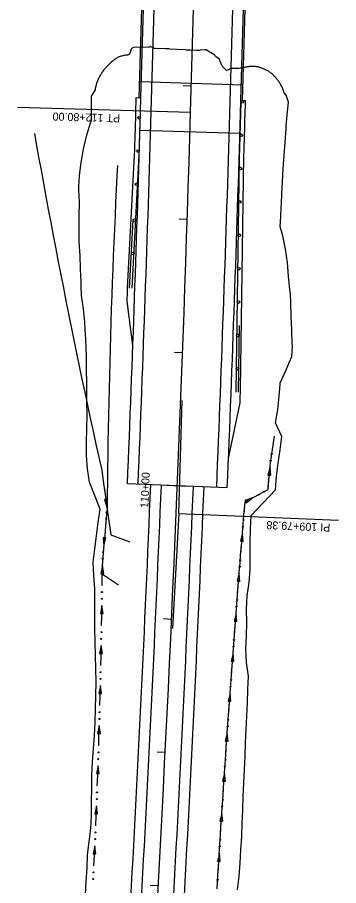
# Model space of a CAD drawing. Extents: x 1441466 to 1476381, y 2042742 to 2057194.
# Drawn here: x 1445977 to 1446218, y 2043457 to 2044108 of the extents above; entities that cross this region are included whole.
import ezdxf

# ---------------------------------------------------------------- set-up
doc = ezdxf.new("R2010")
doc.units = 0
for name, color, linetype in [('Default', 7, 'Continuous'), ('R_Bridge', 7, 'Continuous'), ('R_Guardrail', 7, 'Continuous'), ('R_Horz Alg', 7, 'Continuous'), ('R_Horz Alg Annot', 7, 'Continuous'), ('R_Horz Alg Stationing', 7, 'Continuous'), ('R_Proposed Const Limits', 7, 'Continuous'), ('R_Proposed Road', 7, 'Continuous'), ('R_Shld', 7, 'Continuous'), ('R_Special Ditch', 7, 'Continuous')]:
    doc.layers.add(name, color=color, linetype=linetype)

msp = doc.modelspace()

# ---------------------------------------------------------------- linework, layer by layer
at = {"layer": 'Default'}
for p, q in [((1446043.94, 2043747.07), (1446041.85, 2043746.77)), ((1446041.85, 2043746.77), (1446043.75, 2043740.98)), ((1446043.75, 2043740.98), (1446043.94, 2043747.07)), ((1446043.02, 2043717.95), (1446040.91, 2043718.13)), ((1446040.91, 2043718.13), (1446041.45, 2043712.06)), ((1446041.45, 2043712.06), (1446043.02, 2043717.95)), ((1446040.33, 2043697.27), (1446039.22, 2043691.28)), ((1446041.34, 2043691.26), (1446040.33, 2043697.27)), ((1446039.22, 2043691.28), (1446041.34, 2043691.26)), ((1446039.99, 2043667.23), (1446038.85, 2043661.25)), ((1446040.96, 2043661.22), (1446039.99, 2043667.23)), ((1446038.85, 2043661.25), (1446040.96, 2043661.22)), ((1446039.5, 2043637.2), (1446038.32, 2043631.22)), ((1446040.44, 2043631.18), (1446039.5, 2043637.2)), ((1446038.32, 2043631.22), (1446040.44, 2043631.18)), ((1446038.84, 2043607.18), (1446037.63, 2043601.21)), ((1446039.74, 2043601.15), (1446038.84, 2043607.18)), ((1446037.63, 2043601.21), (1446039.74, 2043601.15)), ((1446038.05, 2043577.15), (1446036.81, 2043571.19)), ((1446038.93, 2043571.12), (1446038.05, 2043577.15)), ((1446036.81, 2043571.19), (1446038.93, 2043571.12)), ((1446037.09, 2043547.13), (1446035.83, 2043541.17)), ((1446037.94, 2043541.1), (1446037.09, 2043547.13)), ((1446035.83, 2043541.17), (1446037.94, 2043541.1)), ((1446035.98, 2043517.11), (1446034.69, 2043511.16)), ((1446036.8, 2043511.07), (1446035.98, 2043517.11)), ((1446034.69, 2043511.16), (1446036.8, 2043511.07)), ((1446034.72, 2043487.1), (1446033.39, 2043481.15)), ((1446035.51, 2043481.06), (1446034.72, 2043487.1)), ((1446033.39, 2043481.15), (1446035.51, 2043481.06))]:
    msp.add_line(p, q, dxfattribs=at)
for points in [[(1445989.4, 2044021.03), (1445990.78, 2044013.22), (1445992.55, 2044003.4), (1445994.32, 2043993.58), (1445996.12, 2043983.77), (1445997.93, 2043973.96), (1445999.76, 2043964.15), (1446001.61, 2043954.34), (1446003.47, 2043944.54), (1446005.35, 2043934.74), (1446007.24, 2043924.95), (1446009.15, 2043915.16), (1446011.08, 2043905.37), (1446013.03, 2043895.58), (1446014.99, 2043885.8), (1446020.97, 2043856.47)], [(1446051.69, 2043997.15), (1446051.28, 2043989.22), (1446050.78, 2043979.26), (1446050.3, 2043969.3), (1446049.84, 2043959.33), (1446049.39, 2043949.36), (1446048.96, 2043939.4), (1446048.54, 2043929.43), (1446048.14, 2043919.46), (1446047.76, 2043909.49), (1446047.4, 2043899.52), (1446047.05, 2043889.55), (1446046.72, 2043879.58), (1446046.41, 2043869.61), (1446046.11, 2043859.63), (1446045.33, 2043829.7)], [(1446020.97, 2043856.47), (1446023, 2043846.7), (1446025.05, 2043836.93), (1446027.11, 2043827.17), (1446029.19, 2043817.41), (1446031.28, 2043807.65), (1446033.39, 2043797.9), (1446035.52, 2043788.15), (1446037.67, 2043778.4), (1446039.85, 2043768.58), (1446040.41, 2043764.55), (1446041.24, 2043758.61), (1446042.64, 2043748.73), (1446044.05, 2043738.85), (1446045.49, 2043728.97), (1446046.76, 2043720.25), (1446060.96, 2043714.93)], [(1446045.33, 2043829.71), (1446045.1, 2043819.73), (1446044.89, 2043809.76), (1446044.69, 2043799.78), (1446044.51, 2043789.8), (1446044.35, 2043779.83), (1446044.21, 2043769.85), (1446044.08, 2043759.87), (1446043.97, 2043749.89), (1446043.88, 2043739.83), (1446043.52, 2043735.77), (1446042.99, 2043729.8), (1446042.12, 2043719.86), (1446041.27, 2043709.91), (1446040.43, 2043699.96), (1446039.71, 2043691.19), (1446052.34, 2043682.79)], [(1446041.63, 2043755.83), (1446042.64, 2043748.73), (1446043.75, 2043740.98)], [(1446044.03, 2043742.15), (1446044.04, 2043742.18)], [(1446042.74, 2043727.01), (1446042.12, 2043719.86), (1446041.45, 2043712.06)], [(1446041.49, 2043712.22), (1446041.49, 2043712.25)], [(1446040.18, 2043682.27), (1446040.26, 2043689.37), (1446040.33, 2043697.27)], [(1446040.18, 2043682.23), (1446040.18, 2043682.27)], [(1446039.76, 2043652.23), (1446039.88, 2043659.44), (1446039.99, 2043667.23)], [(1446039.76, 2043652.19), (1446039.76, 2043652.23)], [(1446039.19, 2043622.2), (1446039.35, 2043629.5), (1446039.5, 2043637.2)], [(1446039.19, 2043622.16), (1446039.19, 2043622.2)], [(1446038.45, 2043592.18), (1446038.84, 2043607.18)], [(1446038.45, 2043592.15), (1446038.45, 2043592.18)], [(1446037.59, 2043562.16), (1446037.82, 2043569.66), (1446038.05, 2043577.15)], [(1446037.59, 2043562.12), (1446037.59, 2043562.16)], [(1446036.56, 2043532.14), (1446036.83, 2043539.74), (1446037.09, 2043547.13)], [(1446036.56, 2043532.1), (1446036.56, 2043532.14)], [(1446035.37, 2043502.12), (1446035.69, 2043509.83), (1446035.98, 2043517.11)], [(1446035.37, 2043502.09), (1446035.37, 2043502.12)], [(1446034.03, 2043472.12), (1446034.4, 2043479.93), (1446034.72, 2043487.1)], [(1446034.03, 2043472.08), (1446034.03, 2043472.12)]]:
    msp.add_lwpolyline(points, dxfattribs=at)
for centre in [(1446043.59, 2043737.18), (1446043.17, 2043732.19), (1446041.01, 2043707.25), (1446040.57, 2043702.26), (1446040.02, 2043672.24), (1446040.09, 2043677.25), (1446039.64, 2043647.21), (1446039.55, 2043642.2), (1446039.05, 2043617.18), (1446038.93, 2043612.17), (1446038.28, 2043587.17), (1446038.15, 2043582.16), (1446037.39, 2043557.14), (1446037.22, 2043552.13), (1446036.14, 2043522.12), (1446036.33, 2043527.12), (1446035.12, 2043497.11), (1446034.9, 2043492.1), (1446033.76, 2043467.1), (1446033.51, 2043462.1)]:
    msp.add_circle(centre, 0.375, dxfattribs=at)
at = {"layer": 'R_Bridge'}
for p, q in [((1446068.06, 2044047.95), (1446071.67, 2044171.9)), ((1446069.31, 2044047.92), (1446072.92, 2044171.86)), ((1446144.28, 2044045.74), (1446147.88, 2044169.68)), ((1446145.53, 2044045.7), (1446149.13, 2044169.65)), ((1446069.31, 2044047.92), (1446068.06, 2044047.95)), ((1446144.28, 2044045.74), (1446145.53, 2044045.7))]:
    msp.add_line(p, q, dxfattribs=at)
for points in [[(1446068.41, 2044059.95), (1446145.88, 2044057.69)], [(1446143.56, 2044021.2), (1446068.59, 2044023.43)]]:
    msp.add_lwpolyline(points, dxfattribs=at)
at = {"layer": 'R_Guardrail'}
for p, q in [((1446060.78, 2043905.17), (1446063.47, 2043956.13)), ((1446142.49, 2043827.13), (1446143.21, 2043877.26))]:
    msp.add_line(p, q, dxfattribs=at)
for points in [[(1446062.78, 2043905.12), (1446068.03, 2044004.76), (1446068.03, 2044004.84), (1446069.02, 2044037.92), (1446069.31, 2044047.91)], [(1446144.25, 2044044.74), (1446143.99, 2044035.74), (1446143, 2044002.55), (1446143, 2044002.5), (1446140.49, 2043827.15)]]:
    msp.add_lwpolyline(points, dxfattribs=at)
for centre in [(1446145.25, 2044044.71), (1446067.87, 2044032.94), (1446144.51, 2044019.72), (1446067.13, 2044007.95), (1446143.89, 2043994.74), (1446065.84, 2043983.01), (1446143.53, 2043969.75), (1446064.46, 2043956.04), (1446143.17, 2043944.75), (1446063.15, 2043931.08), (1446142.81, 2043919.75), (1446142.46, 2043894.75), (1446142.1, 2043869.76), (1446141.74, 2043844.76)]:
    msp.add_circle(centre, 1, dxfattribs=at)
at = {"layer": 'R_Horz Alg'}
msp.add_line((1446106.5, 2044036.83), (1446111.16, 2044196.76), dxfattribs=at)
msp.add_arc((1423197.89, 2044703.4), 22918.31, 356.830169, 358.333333, dxfattribs=at)
at = {"layer": 'R_Horz Alg Annot'}
for q in [(1446100.22, 2043820.87), (1446092.97, 2043649.91)]:
    msp.add_line((1446097.76, 2043736.31), q, dxfattribs=at)
for points in [[(1446106.5, 2044036.83), (1445976.56, 2044040.61)], [(1446097.76, 2043736.31), (1446217.65, 2043731.24)]]:
    msp.add_lwpolyline(points, dxfattribs=at)
at = {"layer": 'R_Horz Alg Stationing'}
for points in [[(1446101.09, 2044057), (1446107.08, 2044056.82)], [(1446098.04, 2043957.06), (1446104.04, 2043956.87)], [(1446094.56, 2043857.15), (1446100.56, 2043856.93)], [(1446088.66, 2043757.34), (1446104.64, 2043756.68)], [(1446086.31, 2043657.37), (1446092.3, 2043657.1)], [(1446081.53, 2043557.51), (1446087.52, 2043557.21)], [(1446076.31, 2043457.68), (1446082.3, 2043457.35)]]:
    msp.add_lwpolyline(points, dxfattribs=at)
at = {"layer": 'R_Proposed Const Limits'}
for points in [[(1446133.55, 2044068.26), (1446131.67, 2044069.98), (1446131.19, 2044070.47), (1446130.77, 2044071), (1446130.41, 2044071.57), (1446130.1, 2044072.18), (1446128.55, 2044075.77), (1446128.5, 2044075.88), (1446128.45, 2044075.99), (1446128.41, 2044076.1), (1446128.37, 2044076.21), (1446128.2, 2044076.65), (1446128.15, 2044076.75), (1446128.09, 2044076.84), (1446128.01, 2044076.92), (1446127.92, 2044076.99), (1446126.05, 2044078.22), (1446125.85, 2044078.37), (1446125.66, 2044078.53), (1446125.49, 2044078.7), (1446125.34, 2044078.9), (1446124.75, 2044079.7), (1446124.59, 2044079.89), (1446124.42, 2044080.07), (1446124.22, 2044080.22), (1446124.02, 2044080.35), (1446121.45, 2044081.82), (1446121.11, 2044082.02), (1446120.76, 2044082.23), (1446120.42, 2044082.44), (1446120.07, 2044082.64), (1446118.7, 2044083.49), (1446118.35, 2044083.67), (1446117.99, 2044083.78), (1446117.61, 2044083.84), (1446117.22, 2044083.83), (1446113.74, 2044083.47), (1446113.02, 2044083.41), (1446112.31, 2044083.37), (1446111.59, 2044083.36), (1446110.87, 2044083.38), (1446106.28, 2044083.54), (1446105.28, 2044083.57), (1446104.27, 2044083.62), (1446103.27, 2044083.67), (1446102.26, 2044083.73), (1446091.08, 2044084.4), (1446090.23, 2044084.44), (1446089.39, 2044084.49), (1446088.55, 2044084.52), (1446087.7, 2044084.56), (1446079.86, 2044084.82), (1446079.5, 2044084.86), (1446079.15, 2044084.93), (1446078.81, 2044085.05), (1446078.48, 2044085.21), (1446076.78, 2044086.14), (1446076.66, 2044086.19), (1446076.53, 2044086.21), (1446076.4, 2044086.19), (1446076.28, 2044086.15), (1446075.77, 2044085.9), (1446075.64, 2044085.84), (1446075.5, 2044085.8), (1446075.37, 2044085.78), (1446075.22, 2044085.77), (1446063.82, 2044085.49), (1446063.22, 2044085.4), (1446062.73, 2044085.16), (1446062.34, 2044084.77), (1446062.05, 2044084.24), (1446061.11, 2044081.8), (1446060.85, 2044081.21), (1446060.52, 2044080.66), (1446060.14, 2044080.15), (1446059.98, 2044079.98)], [(1446059.96, 2044079.96), (1446059.86, 2044079.95), (1446059.16, 2044079.9), (1446058.45, 2044079.83), (1446057.75, 2044079.74), (1446057.05, 2044079.64), (1446056.36, 2044079.51), (1446055.66, 2044079.36), (1446054.97, 2044079.19), (1446054.28, 2044079), (1446053.6, 2044078.8), (1446052.93, 2044078.55), (1446052.3, 2044078.21), (1446051.69, 2044077.86), (1446051.08, 2044077.49), (1446050.48, 2044077.11), (1446049.89, 2044076.72), (1446049.31, 2044076.32), (1446048.73, 2044075.91), (1446048.17, 2044075.48), (1446047.61, 2044075.04), (1446047.07, 2044074.59), (1446046.53, 2044074.13), (1446046, 2044073.66), (1446045.49, 2044073.18), (1446044.98, 2044072.69), (1446044.66, 2044072.36), (1446044.48, 2044072.19), (1446044, 2044071.68), (1446043.53, 2044071.16), (1446043.06, 2044070.63), (1446042.61, 2044070.09), (1446042.14, 2044069.57), (1446041.68, 2044069.04), (1446041.23, 2044068.49), (1446040.8, 2044067.94), (1446040.39, 2044067.36), (1446039.99, 2044066.78), (1446039.61, 2044066.19), (1446039.24, 2044065.6), (1446038.87, 2044065), (1446038.52, 2044064.39), (1446038.18, 2044063.77), (1446037.86, 2044063.14), (1446037.55, 2044062.51), (1446037.25, 2044061.88), (1446036.97, 2044061.23), (1446036.7, 2044060.58), (1446036.45, 2044059.93), (1446036.21, 2044059.27), (1446035.99, 2044058.6), (1446035.78, 2044057.94), (1446035.59, 2044057.26), (1446035.41, 2044056.59), (1446035.24, 2044055.91), (1446035.13, 2044055.39)], [(1446176.73, 2044051.6), (1446176.62, 2044052.05), (1446176.44, 2044052.69), (1446176.24, 2044053.31), (1446176.02, 2044053.94), (1446175.79, 2044054.55), (1446175.54, 2044055.16), (1446175.28, 2044055.76), (1446175, 2044056.36), (1446174.71, 2044056.94), (1446174.39, 2044057.52), (1446174.07, 2044058.08), (1446173.73, 2044058.64), (1446173.37, 2044059.18), (1446173, 2044059.72), (1446172.62, 2044060.24), (1446172.22, 2044060.76), (1446171.81, 2044061.26), (1446171.39, 2044061.74), (1446171, 2044062.25), (1446170.6, 2044062.75), (1446170.2, 2044063.24), (1446169.78, 2044063.72), (1446169.35, 2044064.18), (1446168.9, 2044064.63), (1446168.44, 2044065.07), (1446167.97, 2044065.49), (1446167.49, 2044065.9), (1446167, 2044066.3), (1446166.5, 2044066.67), (1446165.99, 2044067.04), (1446165.47, 2044067.39), (1446164.94, 2044067.72), (1446164.4, 2044068.04), (1446163.85, 2044068.34), (1446163.3, 2044068.62), (1446162.74, 2044068.89), (1446162.19, 2044069.17), (1446161.64, 2044069.43), (1446161.09, 2044069.68), (1446160.52, 2044069.92), (1446159.96, 2044070.14), (1446159.39, 2044070.34), (1446158.81, 2044070.52), (1446158.24, 2044070.69), (1446157.66, 2044070.85), (1446157.07, 2044070.98), (1446156.49, 2044071.1), (1446155.89, 2044071.18), (1446155.29, 2044071.24), (1446154.7, 2044071.29), (1446154.1, 2044071.32), (1446153.51, 2044071.33), (1446152.92, 2044071.34), (1446152.34, 2044071.32), (1446151.76, 2044071.3), (1446151.18, 2044071.26), (1446150.61, 2044071.21), (1446150.04, 2044071.14), (1446149.47, 2044071.06), (1446148.91, 2044070.97), (1446148.36, 2044070.87), (1446147.81, 2044070.76), (1446147.27, 2044070.63), (1446146.74, 2044070.52), (1446146.21, 2044070.42), (1446145.69, 2044070.32), (1446145.24, 2044070.2), (1446145.21, 2044070.07), (1446145.19, 2044069.94), (1446145.17, 2044069.94), (1446144.67, 2044069.95), (1446143.67, 2044069.96), (1446142.67, 2044069.93), (1446141.67, 2044069.9), (1446140.67, 2044069.87), (1446139.67, 2044069.84), (1446138.66, 2044069.8), (1446137.66, 2044069.77), (1446136.66, 2044069.74), (1446135.65, 2044069.37), (1446134.63, 2044068.53), (1446133.62, 2044068.28)], [(1446030.59, 2043759.74), (1446029.18, 2043769.77), (1446028.39, 2043779.78), (1446028.52, 2043789.76), (1446028.73, 2043799.73), (1446028.85, 2043809.7), (1446028.75, 2043819.68), (1446028.75, 2043824.67), (1446028.72, 2043829.66), (1446028.59, 2043838.38), (1446028.57, 2043839.64), (1446028.41, 2043849.62), (1446028.33, 2043855.5), (1446028.27, 2043859.6), (1446027.92, 2043867.61), (1446027.79, 2043869.59), (1446027.16, 2043879.59), (1446026.3, 2043889.6), (1446024.65, 2043899.63), (1446024.42, 2043906.47), (1446024.34, 2043909.61), (1446023.94, 2043919.6), (1446023.63, 2043929.58), (1446023.02, 2043939.57), (1446022.88, 2043949.54), (1446023, 2043956.37), (1446023.05, 2043959.51), (1446023.1, 2043969.48), (1446022.67, 2043979.46), (1446022.59, 2043981.31), (1446023.23, 2043989.41), (1446023.26, 2043989.67), (1446024.55, 2043999.34), (1446026.29, 2044009.26), (1446028.46, 2044019.16), (1446031.54, 2044029.04), (1446032.24, 2044030.86), (1446032.27, 2044038.99), (1446032.25, 2044043.99), (1446032.12, 2044049), (1446035.18, 2044053.91), (1446035.13, 2044055.39)], [(1446175.12, 2043793.93), (1446170.33, 2043804.16), (1446172.01, 2043814.13), (1446172.61, 2043819.13), (1446173.05, 2043824.13), (1446173.74, 2043832.88), (1446173.89, 2043834.14), (1446178.17, 2043844.02), (1446180.69, 2043849.84), (1446182.46, 2043853.9), (1446182.91, 2043861.93), (1446182.84, 2043863.93), (1446182.49, 2043873.99), (1446182.14, 2043884.04), (1446181.79, 2043894.09), (1446181.52, 2043900.98), (1446181, 2043904.16), (1446180.1, 2043914.23), (1446179.15, 2043924.3), (1446177.78, 2043934.39), (1446175.76, 2043944.49), (1446173.83, 2043951.43), (1446174.01, 2043954.59), (1446174.53, 2043964.61), (1446175.04, 2043974.63), (1446175.13, 2043976.48), (1446175.52, 2043984.65), (1446175.53, 2043984.91), (1446176.03, 2043994.67), (1446176.7, 2044004.68), (1446177.45, 2044014.7), (1446178.18, 2044024.71), (1446178.31, 2044026.56), (1446179.08, 2044034.72), (1446179.56, 2044039.71), (1446180.04, 2044044.69), (1446178.17, 2044049.75), (1446176.73, 2044051.6)], [(1446141.77, 2043454.11), (1446143.09, 2043464.08), (1446143.74, 2043474.09), (1446144.33, 2043484.1), (1446144.88, 2043494.11), (1446145.27, 2043504.13), (1446145.68, 2043514.15), (1446146.09, 2043524.17), (1446146.52, 2043534.18), (1446146.94, 2043544.2), (1446147.38, 2043554.22), (1446147.83, 2043564.23), (1446148.32, 2043574.25), (1446148.7, 2043584.27), (1446149.17, 2043594.28), (1446149.55, 2043604.3), (1446149.96, 2043614.32), (1446148.51, 2043624.42), (1446147.97, 2043634.49), (1446148.62, 2043644.49), (1446148.76, 2043654.52), (1446148.6, 2043664.56), (1446148.92, 2043674.58), (1446150.45, 2043684.55), (1446151.16, 2043694.55), (1446151.18, 2043698.56), (1446151.22, 2043704.58), (1446151.29, 2043714.61), (1446151.46, 2043724.64), (1446152.08, 2043734.65), (1446170.29, 2043753.96), (1446171.11, 2043763.97), (1446172.29, 2043773.96), (1446173.74, 2043783.94), (1446175.12, 2043793.93)], [(1446035.68, 2043609.75), (1446035.45, 2043619.75), (1446035.21, 2043629.75), (1446034.95, 2043639.75), (1446034.68, 2043649.75), (1446034.68, 2043659.73), (1446034.73, 2043669.72), (1446034.58, 2043679.71), (1446034.04, 2043689.72), (1446033.46, 2043699.72), (1446033.96, 2043703.7), (1446034.71, 2043709.65), (1446035.96, 2043719.58), (1446037.16, 2043729.52), (1446038.68, 2043739.43), (1446030.59, 2043759.74)], [(1446000.8, 2043429.75), (1446017.61, 2043436.13), (1446027.12, 2043444.51), (1446027.62, 2043450.34), (1446028.26, 2043460.29), (1446028.87, 2043470.25), (1446029.22, 2043480.22), (1446030.38, 2043490.15), (1446031.64, 2043500.08), (1446032.09, 2043510.04), (1446032.23, 2043520.03), (1446032.34, 2043530.01), (1446032.42, 2043540), (1446033.06, 2043549.95), (1446033.72, 2043559.91), (1446034.35, 2043569.87), (1446034.94, 2043579.83), (1446035.68, 2043609.75)]]:
    msp.add_lwpolyline(points, dxfattribs=at)
at = {"layer": 'R_Proposed Road'}
for p, q in [((1446077.01, 2044037.69), (1446081.67, 2044197.62)), ((1446135.99, 2044035.97), (1446140.64, 2044195.9)), ((1446069.02, 2044037.92), (1446069.31, 2044047.92)), ((1446143.99, 2044035.74), (1446144.28, 2044045.74)), ((1446134.12, 2043755.46), (1446059.18, 2043758.55))]:
    msp.add_line(p, q, dxfattribs=at)
for radius, start, end in [(22880.81, 357.633333, 358.333333), (22888.81, 357.633333, 358.333333), (22947.81, 357.633333, 358.333333), (22955.81, 357.633333, 358.333333), (22898.31, 356.830169, 357.633333), (22906.31, 356.830169, 357.633333), (22930.31, 356.830169, 357.633333), (22938.31, 356.830169, 357.633333)]:
    msp.add_arc((1423197.89, 2044703.4), radius, start, end, dxfattribs=at)
at = {"layer": 'R_Shld'}
for p, q in [((1446065.46, 2044036.02), (1446065.81, 2044048.02)), ((1446065.81, 2044048.02), (1446068.06, 2044047.95)), ((1446147.78, 2044045.63), (1446145.53, 2044045.7)), ((1446147.43, 2044033.64), (1446147.78, 2044045.63)), ((1446059.28, 2043905.24), (1446064.54, 2044004.94)), ((1446144.05, 2043829.1), (1446146.56, 2044004.45)), ((1446063.23, 2043862.24), (1446058.93, 2043895.27)), ((1446135.01, 2043777.32), (1446143.66, 2043819.09))]:
    msp.add_line(p, q, dxfattribs=at)
for centre, radius, start, end in [((1423197.83, 2044701.4), 22877.31, 358.255458, 358.333333), ((1423197.89, 2044703.4), 22959.31, 358.255458, 358.333333), ((1423197.83, 2044701.4), 22875.31, 357.980458, 358.005458), ((1423197.89, 2044703.4), 22962.81, 357.792958, 357.817958)]:
    msp.add_arc(centre, radius, start, end, dxfattribs=at)
at = {"layer": 'R_Special Ditch'}
for p, q in [((1446166.14, 2043770.91), (1446164.56, 2043765.02)), ((1446166.67, 2043764.84), (1446166.14, 2043770.91)), ((1446164.56, 2043765.02), (1446166.67, 2043764.84)), ((1446153.02, 2043747.9), (1446147.24, 2043745.98)), ((1446147.24, 2043745.98), (1446148.24, 2043744.12)), ((1446148.24, 2043744.12), (1446153.02, 2043747.9)), ((1446145.46, 2043721.29), (1446143.91, 2043715.4)), ((1446146.02, 2043715.22), (1446145.46, 2043721.29)), ((1446143.91, 2043715.4), (1446146.02, 2043715.22)), ((1446143.03, 2043691.35), (1446141.5, 2043685.45)), ((1446141.5, 2043685.45), (1446143.61, 2043685.28)), ((1446143.61, 2043685.28), (1446143.03, 2043691.35)), ((1446140.68, 2043661.4), (1446139.17, 2043655.5)), ((1446141.28, 2043655.34), (1446140.68, 2043661.4)), ((1446139.17, 2043655.5), (1446141.28, 2043655.34)), ((1446138.41, 2043631.45), (1446136.91, 2043625.55)), ((1446139.02, 2043625.39), (1446138.41, 2043631.45)), ((1446136.91, 2043625.55), (1446139.02, 2043625.39)), ((1446136.2, 2043601.49), (1446134.72, 2043595.59)), ((1446136.83, 2043595.43), (1446136.2, 2043601.49)), ((1446134.72, 2043595.59), (1446136.83, 2043595.43)), ((1446134.07, 2043571.53), (1446132.6, 2043565.62)), ((1446134.71, 2043565.47), (1446134.07, 2043571.53)), ((1446132.6, 2043565.62), (1446134.71, 2043565.47)), ((1446132.02, 2043541.56), (1446130.56, 2043535.65)), ((1446130.56, 2043535.65), (1446132.67, 2043535.51)), ((1446132.67, 2043535.51), (1446132.02, 2043541.56)), ((1446130.04, 2043511.59), (1446128.59, 2043505.67)), ((1446130.71, 2043505.54), (1446130.04, 2043511.59)), ((1446128.59, 2043505.67), (1446130.71, 2043505.54)), ((1446128.13, 2043481.61), (1446126.7, 2043475.69)), ((1446128.81, 2043475.56), (1446128.13, 2043481.61)), ((1446126.7, 2043475.69), (1446128.81, 2043475.56))]:
    msp.add_line(p, q, dxfattribs=at)
for points in [[(1446126.49, 2043454.94), (1446127.1, 2043464.95), (1446127.71, 2043474.95), (1446128.34, 2043484.95), (1446128.97, 2043494.95), (1446129.61, 2043504.95), (1446130.25, 2043514.95), (1446130.91, 2043524.95), (1446131.57, 2043534.94), (1446132.25, 2043544.94), (1446132.93, 2043554.94), (1446133.62, 2043564.94), (1446134.31, 2043574.94), (1446135.02, 2043584.93), (1446135.73, 2043594.93), (1446136.45, 2043604.93), (1446137.18, 2043614.93), (1446137.92, 2043624.92), (1446138.67, 2043634.92), (1446139.42, 2043644.92), (1446140.18, 2043654.91), (1446140.95, 2043664.91), (1446141.73, 2043674.9), (1446142.52, 2043684.9), (1446143.32, 2043694.9), (1446143.64, 2043698.89), (1446144.12, 2043704.89), (1446144.93, 2043714.89), (1446145.75, 2043724.88), (1446146.58, 2043734.88), (1446147.42, 2043744.88), (1446164.7, 2043754.19), (1446165.55, 2043764.2), (1446166.42, 2043774.2), (1446167.92, 2043784.18), (1446169.43, 2043794.16)], [(1446168.17, 2043785.8), (1446169.43, 2043794.16)], [(1446168.16, 2043785.76), (1446168.17, 2043785.8)], [(1446164.85, 2043755.96), (1446165.55, 2043764.2), (1446166.14, 2043770.91)], [(1446164.85, 2043755.92), (1446164.85, 2043755.96)], [(1446146.7, 2043736.28), (1446147.42, 2043744.88), (1446153.02, 2043747.9)], [(1446146.69, 2043736.24), (1446146.7, 2043736.27)], [(1446144.24, 2043706.34), (1446144.93, 2043714.89), (1446145.46, 2043721.29)], [(1446144.23, 2043706.3), (1446144.24, 2043706.34)], [(1446141.85, 2043676.4), (1446142.52, 2043684.9), (1446143.03, 2043691.35)], [(1446141.85, 2043676.36), (1446141.85, 2043676.39)], [(1446139.54, 2043646.45), (1446140.18, 2043654.91), (1446140.68, 2043661.4)], [(1446139.53, 2043646.41), (1446139.54, 2043646.45)], [(1446137.3, 2043616.49), (1446137.92, 2043624.92), (1446138.41, 2043631.45)], [(1446137.29, 2043616.45), (1446137.3, 2043616.49)], [(1446135.13, 2043586.53), (1446135.73, 2043594.93), (1446136.2, 2043601.49)], [(1446135.13, 2043586.49), (1446135.13, 2043586.53)], [(1446133.04, 2043556.57), (1446133.62, 2043564.94), (1446134.07, 2043571.53)], [(1446133.04, 2043556.53), (1446133.04, 2043556.57)], [(1446131.02, 2043526.6), (1446131.57, 2043534.94), (1446132.02, 2043541.56)], [(1446131.02, 2043526.56), (1446131.02, 2043526.6)], [(1446129.07, 2043496.62), (1446129.61, 2043504.95), (1446130.04, 2043511.59)], [(1446129.07, 2043496.58), (1446129.07, 2043496.62)], [(1446127.2, 2043466.64), (1446127.71, 2043474.95), (1446128.13, 2043481.61)], [(1446127.2, 2043466.6), (1446127.2, 2043466.64)]]:
    msp.add_lwpolyline(points, dxfattribs=at)
for centre in [(1446167.38, 2043780.84), (1446166.64, 2043775.89), (1446157.41, 2043750.31), (1446161.82, 2043752.68), (1446146.24, 2043731.27), (1446145.83, 2043726.28), (1446143.8, 2043701.34), (1446143.4, 2043696.34), (1446141.03, 2043666.4), (1446141.42, 2043671.39), (1446139.12, 2043641.44), (1446138.74, 2043636.45), (1446136.89, 2043611.49), (1446136.53, 2043606.49), (1446134.74, 2043581.53), (1446134.39, 2043576.53), (1446132.66, 2043551.56), (1446132.32, 2043546.56), (1446130.33, 2043516.59), (1446130.65, 2043521.59), (1446128.72, 2043491.61), (1446128.41, 2043486.61), (1446126.86, 2043461.63)]:
    msp.add_circle(centre, 0.375, dxfattribs=at)

# ---------------------------------------------------------------- texts
at = {"layer": 'R_Horz Alg Annot'}
for s, rotation, p in [('PT 112+80.00', 178.33333, (1446053.73, 2044035.36)), ('PI 109+79.38', 177.58175, (1446211.53, 2043728.5))]:
    msp.add_text(s, height=6, rotation=rotation, dxfattribs=at).set_placement(p)
at = {"layer": 'R_Horz Alg Stationing'}
msp.add_text('110+00', height=6, rotation=87.63333, dxfattribs=at).set_placement((1446074.85, 2043740.12))

doc.saveas('drawing.dxf')
